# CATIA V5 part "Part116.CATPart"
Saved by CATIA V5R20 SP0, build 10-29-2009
Part number: FA 084700-1
Revision: ANY
Definition: UNKNOWN
Nomenclature: FA 084700-1
Source: Unknown
Bounding box of the stored display mesh (mm): x -2.853 to 2.853, y 0.2 to 2.5, z -3 to 3
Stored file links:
  C:\Users\Utente\Desktop\IO LAVORO\3D X SITO CF\CUMSA\3D files FA\FA 084700\Part116.CATPart

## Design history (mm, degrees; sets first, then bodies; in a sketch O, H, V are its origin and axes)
Body1 "Cortar-Extruir1" (main body)
  Solid1: solid without history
